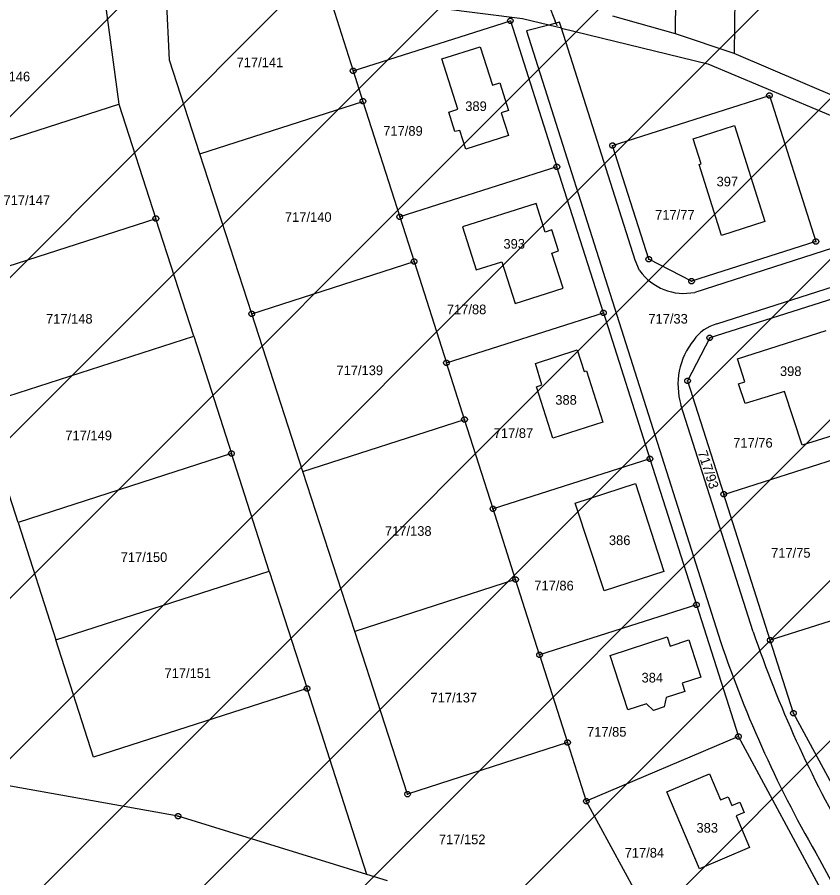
# Model space of a CAD drawing. Extents: x -593358 to -590116, y -1072518 to -1068420.
# Drawn here: x -591520.7 to -591378.7, y -1070287.1 to -1070135.4 of the extents above; entities that cross this region are included whole.
import ezdxf

# ---------------------------------------------------------------- set-up
doc = ezdxf.new("R2010")
doc.units = 0
for name, color, linetype in [('Parcela KN', 7, 'Continuous'), ('Parcela ZE', 7, 'Continuous'), ('Parcelní číslo', 7, 'Continuous'), ('Parcelní číslo_stavební', 7, 'Continuous'), ('Vrstva 16', 7, 'Continuous'), ('Vrstva 24', 7, 'Continuous'), ('zastavitelné území', 7, 'Continuous')]:
    doc.layers.add(name, color=color, linetype=linetype)

msp = doc.modelspace()

# ---------------------------------------------------------------- linework, layer by layer
at = {"layer": 'Parcela KN'}
for p, q in [((-591505.54, -1070130.18), (-591502.78, -1070150.74)), ((-591493.88, -1070143.02), (-591494.5, -1070130.49)), ((-591431.64, -1070135.72), (-591465.82, -1070131.33)), ((-591465.82, -1070131.33), (-591461.49, -1070144.9)), ((-591427.02, -1070136.84), (-591431.64, -1070135.72)), ((-591461.49, -1070144.9), (-591433.79, -1070136.08)), ((-591433.79, -1070136.08), (-591425.59, -1070161.8)), ((-591427.02, -1070136.84), (-591430.93, -1070137.87)), ((-591425.11, -1070136.34), (-591427.02, -1070136.84)), ((-591424.78, -1070137.38), (-591427.02, -1070136.84)), ((-591424.78, -1070137.38), (-591425.11, -1070136.34)), ((-591424.78, -1070137.38), (-591399, -1070143.63)), ((-591411.79, -1070178.23), (-591424.78, -1070137.38)), ((-591430.93, -1070137.87), (-591396.74, -1070245.45)), ((-591445.86, -1070142.77), (-591439.1, -1070140.67)), ((-591439.1, -1070140.67), (-591436.96, -1070147.4)), ((-591488.53, -1070159.53), (-591493.88, -1070143.02)), ((-591443.04, -1070151.66), (-591445.86, -1070142.77)), ((-591461.49, -1070144.9), (-591459.78, -1070150.27)), ((-591399, -1070143.63), (-591373.89, -1070154.22)), ((-591436.96, -1070147.4), (-591435.67, -1070147.01)), ((-591435.67, -1070147.01), (-591434.13, -1070151.88)), ((-591415.77, -1070158.06), (-591388.13, -1070149.24)), ((-591388.13, -1070149.24), (-591379.94, -1070174.97)), ((-591538.74, -1070162.31), (-591502.78, -1070150.74)), ((-591502.78, -1070150.74), (-591496.27, -1070170.94)), ((-591488.53, -1070159.53), (-591459.78, -1070150.27)), ((-591459.78, -1070150.27), (-591453.28, -1070170.62)), ((-591444.64, -1070152.2), (-591443.04, -1070151.66)), ((-591443.56, -1070155.61), (-591444.64, -1070152.2)), ((-591434.13, -1070151.88), (-591435.39, -1070152.27)), ((-591435.39, -1070152.27), (-591434.13, -1070156.3)), ((-591442.72, -1070155.38), (-591443.56, -1070155.61)), ((-591441.65, -1070158.67), (-591442.72, -1070155.38)), ((-591401.55, -1070156.85), (-591394.29, -1070154.52)), ((-591394.29, -1070154.52), (-591388.93, -1070171.44)), ((-591434.13, -1070156.3), (-591441.65, -1070158.67)), ((-591400.16, -1070161.28), (-591401.55, -1070156.85)), ((-591409.39, -1070178.07), (-591415.77, -1070158.06)), ((-591479.37, -1070187.72), (-591488.53, -1070159.53)), ((-591400.53, -1070161.4), (-591400.16, -1070161.28)), ((-591396.58, -1070173.9), (-591400.53, -1070161.4)), ((-591425.59, -1070161.8), (-591453.28, -1070170.62)), ((-591417.39, -1070187.53), (-591425.59, -1070161.8)), ((-591429.25, -1070168.25), (-591442.25, -1070172.38)), ((-591427.68, -1070173.29), (-591429.25, -1070168.25)), ((-591453.28, -1070170.62), (-591450.76, -1070178.51)), ((-591358.35, -1070170.17), (-591401.29, -1070183.92)), ((-591496.27, -1070170.94), (-591533.9, -1070183.06)), ((-591489.61, -1070191.64), (-591496.27, -1070170.94)), ((-591388.93, -1070171.44), (-591396.58, -1070173.9)), ((-591442.25, -1070172.38), (-591439.82, -1070179.95)), ((-591426.49, -1070172.9), (-591427.68, -1070173.29)), ((-591425.28, -1070176.62), (-591426.49, -1070172.9)), ((-591379.94, -1070174.97), (-591401.85, -1070181.95)), ((-591426.46, -1070177.01), (-591425.28, -1070176.62)), ((-591424.49, -1070183.2), (-591426.46, -1070177.01)), ((-591411.01, -1070180.1), (-591411.79, -1070178.23)), ((-591401.85, -1070181.95), (-591409.39, -1070178.07)), ((-591397.42, -1070189.49), (-591359.52, -1070177.34)), ((-591479.37, -1070187.72), (-591450.76, -1070178.51)), ((-591450.76, -1070178.51), (-591445.06, -1070196.34)), ((-591439.82, -1070179.95), (-591435.29, -1070178.53)), ((-591435.29, -1070178.53), (-591432.95, -1070185.9)), ((-591432.95, -1070185.9), (-591424.49, -1070183.2)), ((-591376.75, -1070184.98), (-591398.66, -1070191.96)), ((-591470.35, -1070215.5), (-591479.37, -1070187.72)), ((-591445.06, -1070196.34), (-591417.39, -1070187.53)), ((-591417.39, -1070187.53), (-591409.19, -1070213.25)), ((-591527.24, -1070203.75), (-591489.61, -1070191.64)), ((-591489.61, -1070191.64), (-591482.95, -1070212.33)), ((-591398.66, -1070191.96), (-591402.55, -1070199.5)), ((-591393.76, -1070195.61), (-591378.12, -1070190.66)), ((-591429.38, -1070196.43), (-591422, -1070194.07)), ((-591422, -1070194.07), (-591420.8, -1070197.86)), ((-591441.87, -1070206.33), (-591445.06, -1070196.34)), ((-591428.24, -1070200.19), (-591429.38, -1070196.43)), ((-591392.49, -1070199.67), (-591393.76, -1070195.61)), ((-591420.8, -1070197.86), (-591420.37, -1070197.74)), ((-591420.37, -1070197.74), (-591417.5, -1070206.82)), ((-591402.55, -1070199.5), (-591396.18, -1070219.51)), ((-591429.21, -1070200.56), (-591428.24, -1070200.19)), ((-591426.33, -1070209.61), (-591429.21, -1070200.56)), ((-591393.6, -1070200.06), (-591392.49, -1070199.67)), ((-591392.43, -1070203.52), (-591393.6, -1070200.06)), ((-591385.49, -1070201.38), (-591392.43, -1070203.52)), ((-591382.34, -1070210.86), (-591385.49, -1070201.38)), ((-591520.57, -1070224.45), (-591527.24, -1070203.75)), ((-591390.97, -1070243.76), (-591403.72, -1070203.75)), ((-591470.35, -1070215.5), (-591441.87, -1070206.33)), ((-591436.85, -1070222.06), (-591441.87, -1070206.33)), ((-591417.5, -1070206.82), (-591426.33, -1070209.61)), ((-591374.57, -1070208.41), (-591382.34, -1070210.86)), ((-591396.18, -1070219.51), (-591368.55, -1070210.7)), ((-591482.95, -1070212.33), (-591520.57, -1070224.45)), ((-591476.28, -1070233.02), (-591482.95, -1070212.33)), ((-591409.19, -1070213.25), (-591436.85, -1070222.06)), ((-591409.19, -1070213.25), (-591400.99, -1070238.98)), ((-591461.21, -1070243.65), (-591470.35, -1070215.5)), ((-591422.34, -1070221.05), (-591411.76, -1070217.6)), ((-591411.76, -1070217.6), (-591406.72, -1070233.13)), ((-591387.97, -1070245.23), (-591396.18, -1070219.51)), ((-591432.87, -1070234.53), (-591436.85, -1070222.06)), ((-591417.28, -1070236.54), (-591422.34, -1070221.05)), ((-591520.57, -1070224.45), (-591513.91, -1070245.14)), ((-591513.91, -1070245.14), (-591476.28, -1070233.02)), ((-591476.28, -1070233.02), (-591469.62, -1070253.72)), ((-591406.72, -1070233.13), (-591417.28, -1070236.54)), ((-591432.87, -1070234.53), (-591461.21, -1070243.65)), ((-591428.64, -1070247.78), (-591432.87, -1070234.53)), ((-591360.35, -1070236.42), (-591387.97, -1070245.23)), ((-591400.99, -1070238.98), (-591428.64, -1070247.78)), ((-591400.99, -1070238.98), (-591393.59, -1070262.18)), ((-591451.91, -1070272.32), (-591461.21, -1070243.65)), ((-591416.22, -1070247.9), (-591406.14, -1070244.64)), ((-591406.14, -1070244.64), (-591405.63, -1070246.25)), ((-591507.25, -1070265.83), (-591513.91, -1070245.14)), ((-591405.63, -1070246.25), (-591402.32, -1070245.17)), ((-591402.32, -1070245.17), (-591400.23, -1070251.7)), ((-591383.9, -1070258.05), (-591387.97, -1070245.23)), ((-591428.64, -1070247.78), (-591423.7, -1070263.24)), ((-591413.11, -1070257.49), (-591416.22, -1070247.9)), ((-591400.23, -1070251.7), (-591403.51, -1070252.79)), ((-591469.62, -1070253.72), (-591507.25, -1070265.83)), ((-591459.06, -1070286.51), (-591469.62, -1070253.72)), ((-591403.51, -1070252.79), (-591403.05, -1070254.23)), ((-591406.32, -1070255.3), (-591406.7, -1070256.95)), ((-591403.05, -1070254.23), (-591406.32, -1070255.3)), ((-591409.82, -1070256.42), (-591413.11, -1070257.49)), ((-591408.58, -1070257.6), (-591409.82, -1070256.42)), ((-591406.7, -1070256.95), (-591408.58, -1070257.6)), ((-591374.81, -1070274.84), (-591383.9, -1070258.05)), ((-591423.7, -1070263.24), (-591451.91, -1070272.32)), ((-591423.7, -1070263.24), (-591420.4, -1070273.59)), ((-591393.59, -1070262.18), (-591420.4, -1070273.59)), ((-591376.47, -1070293.83), (-591393.59, -1070262.18)), ((-591492.36, -1070276.22), (-591534.37, -1070268.69)), ((-591406.21, -1070271.9), (-591398.7, -1070268.74)), ((-591398.7, -1070268.74), (-591396.76, -1070273.34)), ((-591400.46, -1070285.48), (-591406.21, -1070271.9)), ((-591420.4, -1070273.59), (-591411.76, -1070289.56)), ((-591396.76, -1070273.34), (-591395.41, -1070272.78)), ((-591395.41, -1070272.78), (-591394.74, -1070274.33)), ((-591394.74, -1070274.33), (-591393.37, -1070273.76)), ((-591393.37, -1070273.76), (-591392.6, -1070275.54)), ((-591459.06, -1070286.51), (-591492.36, -1070276.22)), ((-591392.6, -1070275.54), (-591393.97, -1070276.13)), ((-591393.97, -1070276.13), (-591391.61, -1070281.76)), ((-591391.61, -1070281.76), (-591400.46, -1070285.48)), ((-591379.3, -1070283.84), (-591366.13, -1070308.29)), ((-591455.44, -1070287.63), (-591459.06, -1070286.51))]:
    msp.add_line(p, q, dxfattribs=at)
for centre, radius, start, end in [((-591403.182, -1070174.458), 9.649, 215.78105, 281.30889), ((-591395.634, -1070196.311), 7.051, 104.67576, 145.72601), ((-591391.896, -1070200.163), 12.356, 140.71844, 196.87422), ((-591198.98, -1070178.927), 202.641, 198.6592, 210.3277), ((-591197.549, -1070178.117), 210.264, 198.67695, 210.18622)]:
    msp.add_arc(centre, radius, start, end, dxfattribs=at)
at = {"layer": 'Parcela ZE'}
for p, q in [((-591393.69, -1070092.92), (-591394.33, -1070141.82)), ((-591404.7, -1070138.4), (-591404.1, -1070095.27)), ((-591404.7, -1070138.4), (-591415.72, -1070135.29)), ((-591394.33, -1070141.82), (-591404.7, -1070138.4)), ((-591375.8, -1070149.77), (-591394.33, -1070141.82))]:
    msp.add_line(p, q, dxfattribs=at)
at = {"layer": 'Vrstva 16'}
for p in [(-591427.005, -1070133.343), (-591425.53, -1070136.94)]:
    msp.add_line(p, (-591425.87, -1070136.12), dxfattribs=at)
at = {"layer": 'Vrstva 24'}
for p, q in [((-591433.91, -1070136.08), (-591433.67, -1070136.08)), ((-591461.61, -1070144.9), (-591461.37, -1070144.9)), ((-591388.25, -1070149.24), (-591388.01, -1070149.24)), ((-591459.9, -1070150.27), (-591459.66, -1070150.27)), ((-591415.89, -1070158.06), (-591415.65, -1070158.06)), ((-591425.71, -1070161.8), (-591425.47, -1070161.8)), ((-591453.4, -1070170.62), (-591453.16, -1070170.62)), ((-591496.39, -1070170.94), (-591496.15, -1070170.94)), ((-591380.06, -1070174.97), (-591379.82, -1070174.97)), ((-591409.51, -1070178.07), (-591409.27, -1070178.07)), ((-591450.88, -1070178.51), (-591450.64, -1070178.51)), ((-591401.97, -1070181.95), (-591401.73, -1070181.95)), ((-591479.49, -1070187.72), (-591479.25, -1070187.72)), ((-591417.51, -1070187.53), (-591417.27, -1070187.53)), ((-591398.78, -1070191.96), (-591398.54, -1070191.96)), ((-591445.18, -1070196.34), (-591444.94, -1070196.34)), ((-591402.67, -1070199.5), (-591402.43, -1070199.5)), ((-591441.99, -1070206.33), (-591441.75, -1070206.33)), ((-591483.07, -1070212.33), (-591482.83, -1070212.33)), ((-591409.31, -1070213.25), (-591409.07, -1070213.25)), ((-591396.3, -1070219.51), (-591396.06, -1070219.51)), ((-591436.97, -1070222.06), (-591436.73, -1070222.06)), ((-591432.99, -1070234.53), (-591432.75, -1070234.53)), ((-591401.11, -1070238.98), (-591400.87, -1070238.98)), ((-591388.09, -1070245.23), (-591387.85, -1070245.23)), ((-591428.76, -1070247.78), (-591428.52, -1070247.78)), ((-591469.74, -1070253.72), (-591469.5, -1070253.72)), ((-591384.02, -1070258.05), (-591383.78, -1070258.05)), ((-591423.82, -1070263.24), (-591423.58, -1070263.24)), ((-591393.71, -1070262.18), (-591393.47, -1070262.18)), ((-591452.03, -1070272.32), (-591451.79, -1070272.32)), ((-591420.52, -1070273.59), (-591420.28, -1070273.59)), ((-591492.48, -1070276.22), (-591492.24, -1070276.22))]:
    msp.add_line(p, q, dxfattribs=at)
for points in [[(-591433.64, -1070135.6), (-591433.39, -1070135.78), (-591433.29, -1070136.07), (-591433.39, -1070136.36), (-591433.64, -1070136.54), (-591433.95, -1070136.54), (-591434.2, -1070136.36), (-591434.3, -1070136.07), (-591434.2, -1070135.78), (-591433.95, -1070135.6)], [(-591461.34, -1070144.42), (-591461.09, -1070144.6), (-591460.99, -1070144.89), (-591461.09, -1070145.18), (-591461.34, -1070145.36), (-591461.65, -1070145.36), (-591461.9, -1070145.18), (-591462, -1070144.89), (-591461.9, -1070144.6), (-591461.65, -1070144.42)], [(-591387.98, -1070148.76), (-591387.73, -1070148.94), (-591387.63, -1070149.23), (-591387.73, -1070149.52), (-591387.98, -1070149.7), (-591388.29, -1070149.7), (-591388.54, -1070149.52), (-591388.64, -1070149.23), (-591388.54, -1070148.94), (-591388.29, -1070148.76)], [(-591459.63, -1070149.79), (-591459.38, -1070149.97), (-591459.28, -1070150.26), (-591459.38, -1070150.55), (-591459.63, -1070150.73), (-591459.94, -1070150.73), (-591460.19, -1070150.55), (-591460.29, -1070150.26), (-591460.19, -1070149.97), (-591459.94, -1070149.79)], [(-591415.62, -1070157.58), (-591415.37, -1070157.76), (-591415.27, -1070158.05), (-591415.37, -1070158.34), (-591415.62, -1070158.52), (-591415.93, -1070158.52), (-591416.18, -1070158.34), (-591416.28, -1070158.05), (-591416.18, -1070157.76), (-591415.93, -1070157.58)], [(-591425.44, -1070161.32), (-591425.19, -1070161.5), (-591425.09, -1070161.79), (-591425.19, -1070162.08), (-591425.44, -1070162.26), (-591425.75, -1070162.26), (-591426, -1070162.08), (-591426.1, -1070161.79), (-591426, -1070161.5), (-591425.75, -1070161.32)], [(-591496.12, -1070170.46), (-591495.87, -1070170.64), (-591495.77, -1070170.93), (-591495.87, -1070171.22), (-591496.12, -1070171.4), (-591496.43, -1070171.4), (-591496.68, -1070171.22), (-591496.78, -1070170.93), (-591496.68, -1070170.64), (-591496.43, -1070170.46)], [(-591453.13, -1070170.14), (-591452.88, -1070170.32), (-591452.78, -1070170.61), (-591452.88, -1070170.9), (-591453.13, -1070171.08), (-591453.44, -1070171.08), (-591453.69, -1070170.9), (-591453.79, -1070170.61), (-591453.69, -1070170.32), (-591453.44, -1070170.14)], [(-591379.79, -1070174.49), (-591379.54, -1070174.67), (-591379.44, -1070174.96), (-591379.54, -1070175.25), (-591379.79, -1070175.43), (-591380.1, -1070175.43), (-591380.35, -1070175.25), (-591380.45, -1070174.96), (-591380.35, -1070174.67), (-591380.1, -1070174.49)], [(-591450.61, -1070178.03), (-591450.36, -1070178.21), (-591450.26, -1070178.5), (-591450.36, -1070178.79), (-591450.61, -1070178.97), (-591450.92, -1070178.97), (-591451.17, -1070178.79), (-591451.27, -1070178.5), (-591451.17, -1070178.21), (-591450.92, -1070178.03)], [(-591409.24, -1070177.59), (-591408.99, -1070177.77), (-591408.89, -1070178.06), (-591408.99, -1070178.35), (-591409.24, -1070178.53), (-591409.55, -1070178.53), (-591409.8, -1070178.35), (-591409.9, -1070178.06), (-591409.8, -1070177.77), (-591409.55, -1070177.59)], [(-591401.7, -1070181.47), (-591401.45, -1070181.65), (-591401.35, -1070181.94), (-591401.45, -1070182.23), (-591401.7, -1070182.41), (-591402.01, -1070182.41), (-591402.26, -1070182.23), (-591402.36, -1070181.94), (-591402.26, -1070181.65), (-591402.01, -1070181.47)], [(-591479.22, -1070187.24), (-591478.97, -1070187.42), (-591478.87, -1070187.71), (-591478.97, -1070188), (-591479.22, -1070188.18), (-591479.53, -1070188.18), (-591479.78, -1070188), (-591479.88, -1070187.71), (-591479.78, -1070187.42), (-591479.53, -1070187.24)], [(-591417.24, -1070187.05), (-591416.99, -1070187.23), (-591416.89, -1070187.52), (-591416.99, -1070187.81), (-591417.24, -1070187.99), (-591417.55, -1070187.99), (-591417.8, -1070187.81), (-591417.9, -1070187.52), (-591417.8, -1070187.23), (-591417.55, -1070187.05)], [(-591398.51, -1070191.48), (-591398.26, -1070191.66), (-591398.16, -1070191.95), (-591398.26, -1070192.24), (-591398.51, -1070192.42), (-591398.82, -1070192.42), (-591399.07, -1070192.24), (-591399.17, -1070191.95), (-591399.07, -1070191.66), (-591398.82, -1070191.48)], [(-591444.91, -1070195.86), (-591444.66, -1070196.04), (-591444.56, -1070196.33), (-591444.66, -1070196.62), (-591444.91, -1070196.8), (-591445.22, -1070196.8), (-591445.47, -1070196.62), (-591445.57, -1070196.33), (-591445.47, -1070196.04), (-591445.22, -1070195.86)], [(-591402.4, -1070199.02), (-591402.15, -1070199.2), (-591402.05, -1070199.49), (-591402.15, -1070199.78), (-591402.4, -1070199.96), (-591402.71, -1070199.96), (-591402.96, -1070199.78), (-591403.06, -1070199.49), (-591402.96, -1070199.2), (-591402.71, -1070199.02)], [(-591441.72, -1070205.85), (-591441.47, -1070206.03), (-591441.37, -1070206.32), (-591441.47, -1070206.61), (-591441.72, -1070206.79), (-591442.03, -1070206.79), (-591442.28, -1070206.61), (-591442.38, -1070206.32), (-591442.28, -1070206.03), (-591442.03, -1070205.85)], [(-591482.8, -1070211.85), (-591482.55, -1070212.03), (-591482.45, -1070212.32), (-591482.55, -1070212.61), (-591482.8, -1070212.79), (-591483.11, -1070212.79), (-591483.36, -1070212.61), (-591483.46, -1070212.32), (-591483.36, -1070212.03), (-591483.11, -1070211.85)], [(-591409.04, -1070212.77), (-591408.79, -1070212.95), (-591408.69, -1070213.24), (-591408.79, -1070213.53), (-591409.04, -1070213.71), (-591409.35, -1070213.71), (-591409.6, -1070213.53), (-591409.7, -1070213.24), (-591409.6, -1070212.95), (-591409.35, -1070212.77)], [(-591396.03, -1070219.03), (-591395.78, -1070219.21), (-591395.68, -1070219.5), (-591395.78, -1070219.79), (-591396.03, -1070219.97), (-591396.34, -1070219.97), (-591396.59, -1070219.79), (-591396.69, -1070219.5), (-591396.59, -1070219.21), (-591396.34, -1070219.03)], [(-591436.7, -1070221.58), (-591436.45, -1070221.76), (-591436.35, -1070222.05), (-591436.45, -1070222.34), (-591436.7, -1070222.52), (-591437.01, -1070222.52), (-591437.26, -1070222.34), (-591437.36, -1070222.05), (-591437.26, -1070221.76), (-591437.01, -1070221.58)], [(-591432.72, -1070234.05), (-591432.47, -1070234.23), (-591432.37, -1070234.52), (-591432.47, -1070234.81), (-591432.72, -1070234.99), (-591433.03, -1070234.99), (-591433.28, -1070234.81), (-591433.38, -1070234.52), (-591433.28, -1070234.23), (-591433.03, -1070234.05)], [(-591400.84, -1070238.5), (-591400.59, -1070238.68), (-591400.49, -1070238.97), (-591400.59, -1070239.26), (-591400.84, -1070239.44), (-591401.15, -1070239.44), (-591401.4, -1070239.26), (-591401.5, -1070238.97), (-591401.4, -1070238.68), (-591401.15, -1070238.5)], [(-591387.82, -1070244.75), (-591387.57, -1070244.93), (-591387.47, -1070245.22), (-591387.57, -1070245.51), (-591387.82, -1070245.69), (-591388.13, -1070245.69), (-591388.38, -1070245.51), (-591388.48, -1070245.22), (-591388.38, -1070244.93), (-591388.13, -1070244.75)], [(-591428.49, -1070247.3), (-591428.24, -1070247.48), (-591428.14, -1070247.77), (-591428.24, -1070248.06), (-591428.49, -1070248.24), (-591428.8, -1070248.24), (-591429.05, -1070248.06), (-591429.15, -1070247.77), (-591429.05, -1070247.48), (-591428.8, -1070247.3)], [(-591469.47, -1070253.24), (-591469.22, -1070253.42), (-591469.12, -1070253.71), (-591469.22, -1070254), (-591469.47, -1070254.18), (-591469.78, -1070254.18), (-591470.03, -1070254), (-591470.13, -1070253.71), (-591470.03, -1070253.42), (-591469.78, -1070253.24)], [(-591383.75, -1070257.57), (-591383.5, -1070257.75), (-591383.4, -1070258.04), (-591383.5, -1070258.33), (-591383.75, -1070258.51), (-591384.06, -1070258.51), (-591384.31, -1070258.33), (-591384.41, -1070258.04), (-591384.31, -1070257.75), (-591384.06, -1070257.57)], [(-591393.44, -1070261.7), (-591393.19, -1070261.88), (-591393.09, -1070262.17), (-591393.19, -1070262.46), (-591393.44, -1070262.64), (-591393.75, -1070262.64), (-591394, -1070262.46), (-591394.1, -1070262.17), (-591394, -1070261.88), (-591393.75, -1070261.7)], [(-591423.55, -1070262.76), (-591423.3, -1070262.94), (-591423.2, -1070263.23), (-591423.3, -1070263.52), (-591423.55, -1070263.7), (-591423.86, -1070263.7), (-591424.11, -1070263.52), (-591424.21, -1070263.23), (-591424.11, -1070262.94), (-591423.86, -1070262.76)], [(-591451.76, -1070271.84), (-591451.51, -1070272.02), (-591451.41, -1070272.31), (-591451.51, -1070272.6), (-591451.76, -1070272.78), (-591452.07, -1070272.78), (-591452.32, -1070272.6), (-591452.42, -1070272.31), (-591452.32, -1070272.02), (-591452.07, -1070271.84)], [(-591420.25, -1070273.11), (-591420, -1070273.29), (-591419.9, -1070273.58), (-591420, -1070273.87), (-591420.25, -1070274.05), (-591420.56, -1070274.05), (-591420.81, -1070273.87), (-591420.91, -1070273.58), (-591420.81, -1070273.29), (-591420.56, -1070273.11)], [(-591492.21, -1070275.74), (-591491.96, -1070275.92), (-591491.86, -1070276.21), (-591491.96, -1070276.5), (-591492.21, -1070276.68), (-591492.52, -1070276.68), (-591492.77, -1070276.5), (-591492.87, -1070276.21), (-591492.77, -1070275.92), (-591492.52, -1070275.74)]]:
    msp.add_lwpolyline(points, close=True, dxfattribs=at)
at = {"layer": 'zastavitelné území'}
for p, q in [((-591566.586, -1070197.538), (-591265.792, -1069896.744)), ((-591564.758, -1070223.995), (-591255.654, -1069914.891)), ((-591562.934, -1070250.455), (-591246.309, -1069933.83)), ((-591546.732, -1070262.537), (-591236.963, -1069952.769)), ((-591546.693, -1070290.782), (-591227.618, -1069971.707)), ((-591530.725, -1070303.099), (-591218.628, -1069991.002)), ((-591530.106, -1070330.765), (-591209.771, -1070010.429)), ((-591520.522, -1070349.464), (-591200.819, -1070029.761)), ((-591509.234, -1070366.46), (-591191.409, -1070048.635)), ((-591511.223, -1070396.734), (-591184.75, -1070070.261))]:
    msp.add_line(p, q, dxfattribs=at)

# ---------------------------------------------------------------- texts
at = {"layer": 'Parcelní číslo'}
for s, height, p in [('717/91', 0.1, (-591425.727, -1070136.94)), ('717/141', 1.7, (-591482.043, -1070144.25)), ('717/146', 1.7, (-591526.653, -1070146.75)), ('717/89', 1.7, (-591456.191, -1070156.33)), ('717/147', 1.7, (-591523.133, -1070168.54)), ('717/140', 1.7, (-591473.523, -1070171.5)), ('717/77', 1.7, (-591408.274, -1070171.11)), ('717/88', 1.7, (-591444.981, -1070187.78)), ('717/148', 1.7, (-591515.643, -1070189.43)), ('717/33', 1.7, (-591409.468, -1070189.43)), ('717/139', 1.7, (-591464.443, -1070198.51)), ('717/149', 1.7, (-591512.233, -1070209.98)), ('717/87', 1.7, (-591436.721, -1070209.57)), ('717/76', 1.7, (-591394.514, -1070211.28)), ('717/138', 1.7, (-591455.893, -1070226.82)), ('717/150', 1.7, (-591502.473, -1070231.43)), ('717/75', 1.7, (-591387.831, -1070230.68)), ('717/86', 1.7, (-591429.571, -1070236.44)), ('717/151', 1.7, (-591494.753, -1070251.87)), ('717/137', 1.7, (-591447.873, -1070256.18)), ('717/85', 1.7, (-591420.278, -1070262.21)), ('717/152', 1.7, (-591446.393, -1070281.15)), ('717/84', 1.7, (-591413.641, -1070283.51))]:
    msp.add_text(s, height=height, dxfattribs=at).set_placement(p)
msp.add_text('717/93', height=1.7, rotation=288.14048, dxfattribs=at).set_placement((-591400.787, -1070212.107))
at = {"layer": 'Parcelní číslo_stavební'}
for s, p in [('389', (-591441.738, -1070151.97)), ('397', (-591397.441, -1070165.25)), ('393', (-591435.008, -1070176.23)), ('398', (-591386.271, -1070198.66)), ('388', (-591425.868, -1070203.72)), ('386', (-591416.418, -1070228.45)), ('384', (-591410.668, -1070252.66)), ('383', (-591400.985, -1070279.12))]:
    msp.add_text(s, height=1.7, dxfattribs=at).set_placement(p)

doc.saveas('drawing.dxf')
